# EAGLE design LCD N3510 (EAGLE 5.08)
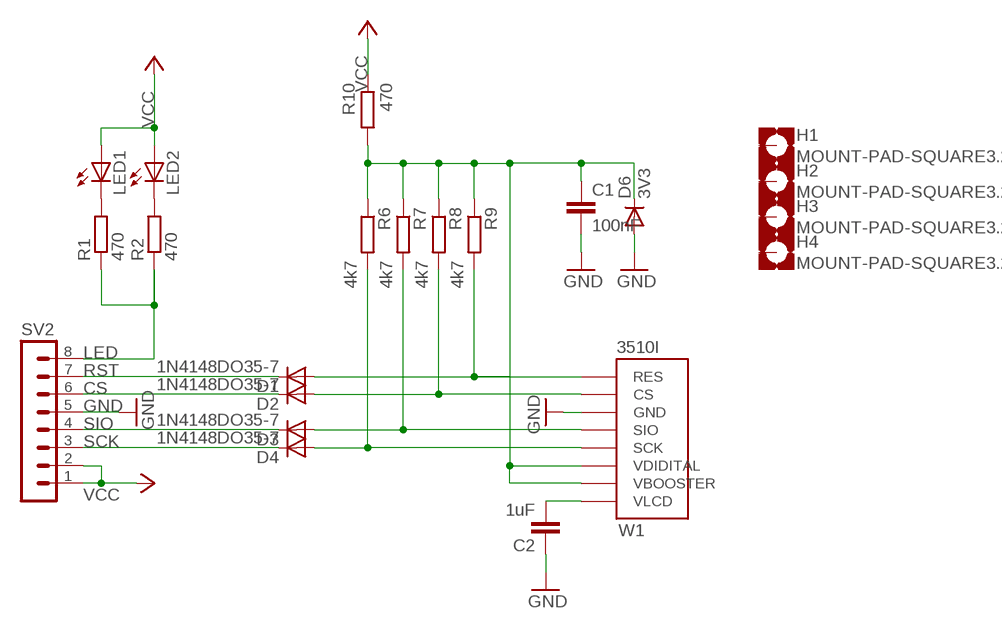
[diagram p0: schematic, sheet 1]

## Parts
C1  100nF  C-EUC1206  [C1206]
C2  1uF  C-EU025_050-025X075  [C025_050-025X075]
D1  1N4148DO35-7  [DO35-7]
D2  1N4148DO35-7  [DO35-7]
D3  1N4148DO35-7  [DO35-7]
D4  1N4148DO35-7  [DO35-7]
D6  3V3  1N4148DO35-7  [DO35-7]
H1  MOUNT-PAD-SQUARE3.2  [3,2-PAD-SQUARE]
H2  MOUNT-PAD-SQUARE3.2  [3,2-PAD-SQUARE]
H3  MOUNT-PAD-SQUARE3.2  [3,2-PAD-SQUARE]
H4  MOUNT-PAD-SQUARE3.2  [3,2-PAD-SQUARE]
LED1  LEDCHIPLED_1206  [CHIPLED_1206]
LED2  LEDCHIPLED_1206  [CHIPLED_1206]
R1  470  R-EU_M1206  [M1206]
R2  470  R-EU_M1206  [M1206]
R6  4k7  R-EU_M1206  [M1206]
R7  4k7  R-EU_M1206  [M1206]
R8  4k7  R-EU_M1206  [M1206]
R9  4k7  R-EU_M1206  [M1206]
R10  470  R-EU_M1206  [M1206]
SV2  MA08-1  [MA08-1]
W1  3510I  [3510I]

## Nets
3V3: C1.1 D6.C R6.1 R7.1 R8.1 R9.1 R10.1 W1.6VDIGITAL(VDIDITAL) W1.7VBOOSTER(VBOOSTER)
CS: D2.C SV2.6
GND: C1.2 C2.1 D6.A SV2.5 W1.3GND(GND)
LED: R1.1 R2.1 SV2.8
N$1: LED1.C R1.2
N$2: LED2.C R2.2
N$3: C2.2 W1.8VLCD(VLCD)
N$5: D1.A R9.2 W1.1RES(RES)
N$6: D2.A R8.2 W1.2CS(CS)
N$7: D3.A R7.2 W1.4SIO(SIO)
N$8: D4.A R6.2 W1.5SCK(SCK)
RST: D1.C SV2.7
SCK: D4.C SV2.3
SIO: D3.C SV2.4
VCC: LED1.A LED2.A R10.2 SV2.1 SV2.2
Unconnected: H1.B3,2(MOUNT) H2.B3,2(MOUNT) H3.B3,2(MOUNT) H4.B3,2(MOUNT)

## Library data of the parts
C1 C2 = rcl:C-EU: CAPACITOR, European symbol
D1-D4 D6 = diode:1N4148: DIODE
H1-H4 = holes:MOUNT-PAD-SQUARE: MOUNTING PAD, square
LED1 LED2 = led:LED: LED
R1 R2 R6-R10 = rcl:R-EU_: RESISTOR, European symbol
SV2 = con-lstb:MA08-1: PIN HEADER
W1 = lcd_nokia_3510i:3510I: Nokia 3510i displayer.

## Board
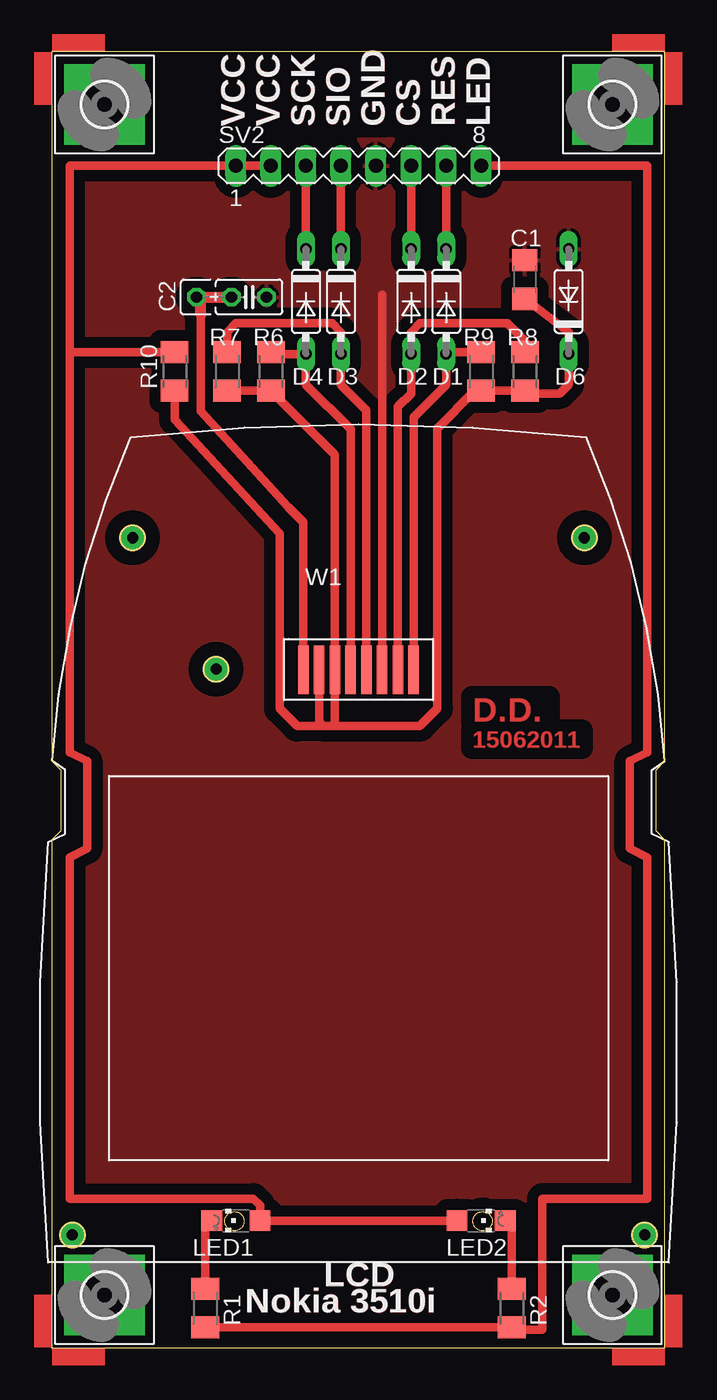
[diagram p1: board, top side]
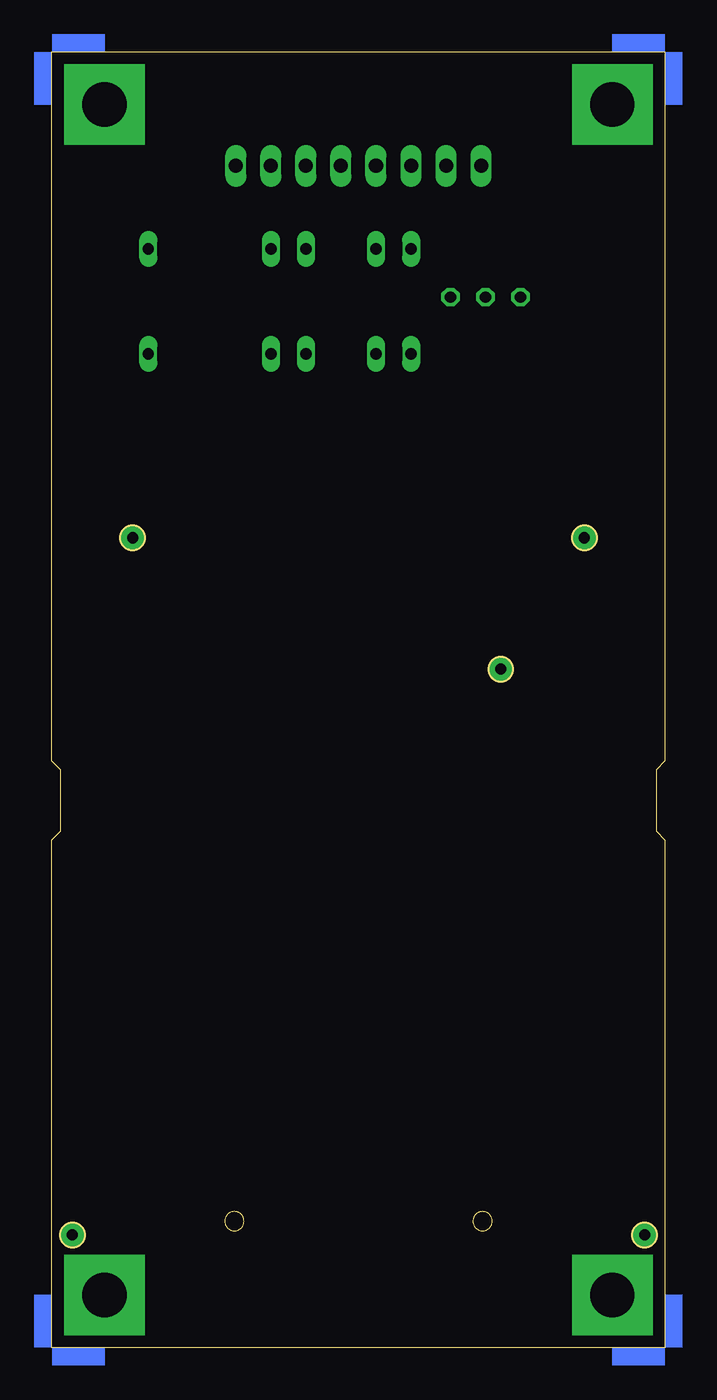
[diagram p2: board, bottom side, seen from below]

Size 44.45 x 93.98 mm. Coordinates in mm from the lower left corner, seen from the top.
Outline: 0,0 44.45,0 44.45,36.83 43.81,37.47 43.81,41.91 44.45,42.55 44.45,93.98 0,93.98 0,42.55 0.64,41.91 0.64,37.47 0,36.83 0,0
Copper layers (1*16): Top 0.035mm / dielectric 1.5mm / Bottom 0.035mm
Design rules "default": minimum track width 10mil, minimum drill 24mil, track to track 8mil, track to pad 8mil, pad to pad 8mil, via to via 8mil, smd to smd 8mil, copper to edge 40mil, drill to drill 8mil, minimum pad ring 10mil, minimum via ring 8mil, stop-mask expansion 4mil, vias tented up to drill 0mil, thermal gap 10mil

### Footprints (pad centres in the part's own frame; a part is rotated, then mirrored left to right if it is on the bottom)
C1206 = smd 1.6 x 1.8: 1 -1.4,0; 2 1.4,0
C025_050-025X075 = drill 0.813 octagon: 1 -1.27,0; 2 1.27,0; 3 3.81,0
DO35-7 = drill 0.813 long: A 3.81,0; C -3.81,0
3,2-PAD-SQUARE = drill 3.2 pad 5.842 square: B3,2 0,0
CHIPLED_1206 = smd 1.5 x 1.5: A 0,-1.75; C 0,1.75
M1206 = smd 1.6 x 2: 1 -1.4,0; 2 1.4,0
MA08-1 = drill 1.016 long: 1 -8.89,0; 2 -6.35,0; 3 -3.81,0; 4 -1.27,0; 5 1.27,0; 6 3.81,0; 7 6.35,0; 8 8.89,0
3510I = smd 0.762 x 3.5: 1RES 4,-1.009; 2CS 2.857,-1.009; 3GND 1.714,-1.009; 4SIO 0.572,-1.009; 5SCK -0.571,-1.009; 6VDIGITAL -1.714,-1.009; 7VBOOSTER -2.857,-1.009; 8VLCD -4,-1.009 | drill 0.8 pad 1.778 round: P$1 -10.319,-0.953; P$6 -16.383,8.572; P$7 16.383,8.572; P$8 20.75,-42; P$9 -20.75,-42

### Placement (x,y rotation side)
C1  34.29,77.47 90 top
C2  14.29,76.2 180 top
D1  28.58,75.88 270 top
D2  26.04,75.88 270 top
D3  20.96,75.88 270 top
D4  18.42,75.88 270 top
D6  37.47,75.88 90 top
H1  3.81,3.81 0 top
H2  40.64,3.81 0 top
H3  40.64,90.17 0 top
H4  3.81,90.17 0 top
LED1  13.34,9.21 90 top
LED2  31.12,9.21 270 top
R1  11.11,2.86 90 top
R2  33.34,2.86 90 top
R6  15.88,70.8 90 top
R7  12.7,70.8 90 top
R8  34.29,70.8 90 top
R9  31.12,70.8 90 top
R10  8.89,70.8 90 top
SV2  22.23,85.72 0 top
U$1  [ANGLE-SE1-16]  0,0 0 top
U$2  [ANGLE-SE1-16]  44.45,0 90 top
U$3  [ANGLE-SE1-16]  44.45,93.98 180 top
U$4  [ANGLE-SE1-16]  0,93.98 270 top
W1  22.23,50.16 0 top

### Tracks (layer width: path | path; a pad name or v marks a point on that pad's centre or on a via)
3V3
  Top 0.61: R7.1 R6.1 20.51,64.77 20.51,60.13 W1.6VDIGITAL 20.51,45.28 20.32,45.09 | C1.1 37.47,73.66 D6.C 37.47,69.85 36.83,69.22 34.48,69.22 R8.1 R9.1 30.67,69.4 27.94,66.67 27.94,46.36 26.67,45.09 20.32,45.09 | 19.69,45.09 17.78,45.09 16.51,46.36 16.51,59.05 8.89,67.31 R10.1 | 19.69,45.09 20.32,45.09 | W1.7VBOOSTER 19.37,45.4 19.69,45.09
CS
  Top 0.61: D2.C SV2.6
GND
  Top 0.61: W1.3GND 23.94,76.39
  pour Top (isolate 0.813): -1.27,95.57 -1.27,-1.27 45.72,-1.27 45.72,95.57
LED
  Top 0.61: R1.1 R2.1 33.53,1.27 35.56,1.27 35.56,10.8 43.18,10.8 43.18,12.07 43.18,35.56 41.91,36.2 41.91,42.55 43.18,43.18 43.18,77.47 43.18,85.72 SV2.8 | SV2.8 31.12,86.36 SV2.8
N$1
  Top 0.61: R1.2 11.11,8.73 LED1.C
N$2
  Top 0.61: R2.2 33.34,8.73 LED2.C
N$3
  Top 0.61: W1.8VLCD 18.23,59.88 17.15,60.96 10.8,67.95 10.8,74.93 | 10.8,76.2 10.16,76.2 10.8,76.2
  Top 0.813: C2.2 10.8,76.2 10.8,74.93
N$5
  Top 0.61: R9.2 28.71,72.2 D1.A 28.58,69.85 26.23,67.5 W1.1RES
N$6
  Top 0.61: R8.2 34.29,73.03 33.02,74.3 26.67,74.3 26.04,73.66 D2.A 26.04,69.22 25.08,68.26 W1.2CS
N$7
  Top 0.61: R7.2 12.7,73.66 13.34,74.3 20.32,74.3 20.96,73.66 D3.A 20.96,69.85 22.8,68.01 W1.4SIO
N$8
  Top 0.61: R6.2 16.01,72.07 D4.A 18.42,69.85 21.65,66.61 W1.5SCK
RST
  Top 0.61: D1.C SV2.7
SCK
  Top 0.61: D4.C SV2.3
SIO
  Top 0.61: D3.C SV2.4
VCC
  Top 0.61: 29.37,9.68 LED2.A LED1.A 15.09,10.32 14.61,10.8 1.27,10.8 1.27,35.56 2.54,36.2 2.54,42.55 1.27,43.18 1.27,72.39 | 1.27,72.39 1.27,85.72 SV2.1 | SV2.1 13.34,86.36 SV2.1 | R10.2 1.46,72.2 1.27,72.39 | SV2.1 SV2.2

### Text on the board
Top: VCC | VCC | SCK | SIO | GND | CS | RES | LED | D.D. | 15062011 | LCD | Nokia 3510i
tNames: VCC | VCC | SCK | SIO | GND | CS | RES | LED | LCD | Nokia 3510i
